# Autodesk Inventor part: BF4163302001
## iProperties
Shininess: 64.0
Angle Display Precision: 2
Document Length Units: 11272
Document Angle Units: 11279
Document Time Units: 11290
Document Mass Units: 11286
Document Length Units Precision: 3
Document Angle Units Precision: 2
Created: 2003-05
Part Number: BF4163302001
Material: Bronze, Soft Tin
Description: 1/8 CAP, PIPE, 125 LB RED BRASS, NPT
Vendor: BF4163302001
Document SubType Name: Modeling
Designer: RCOPE
Density: 8.874
Volumn: 2.048950898054885
Area: 14.455500007908753
PropertySet Name: Model Information
Control State: 0
Master: False
Checked Out: False
Title: CAP, PIPE, 125 LB RED BRASS, NPT
Author: RCOPE
Revision Number: 0
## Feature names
1. Revolution1
2. Extrusion1
3. Extrusion2
4. Extrusion3
5. Fillet1
6. Fillet2
